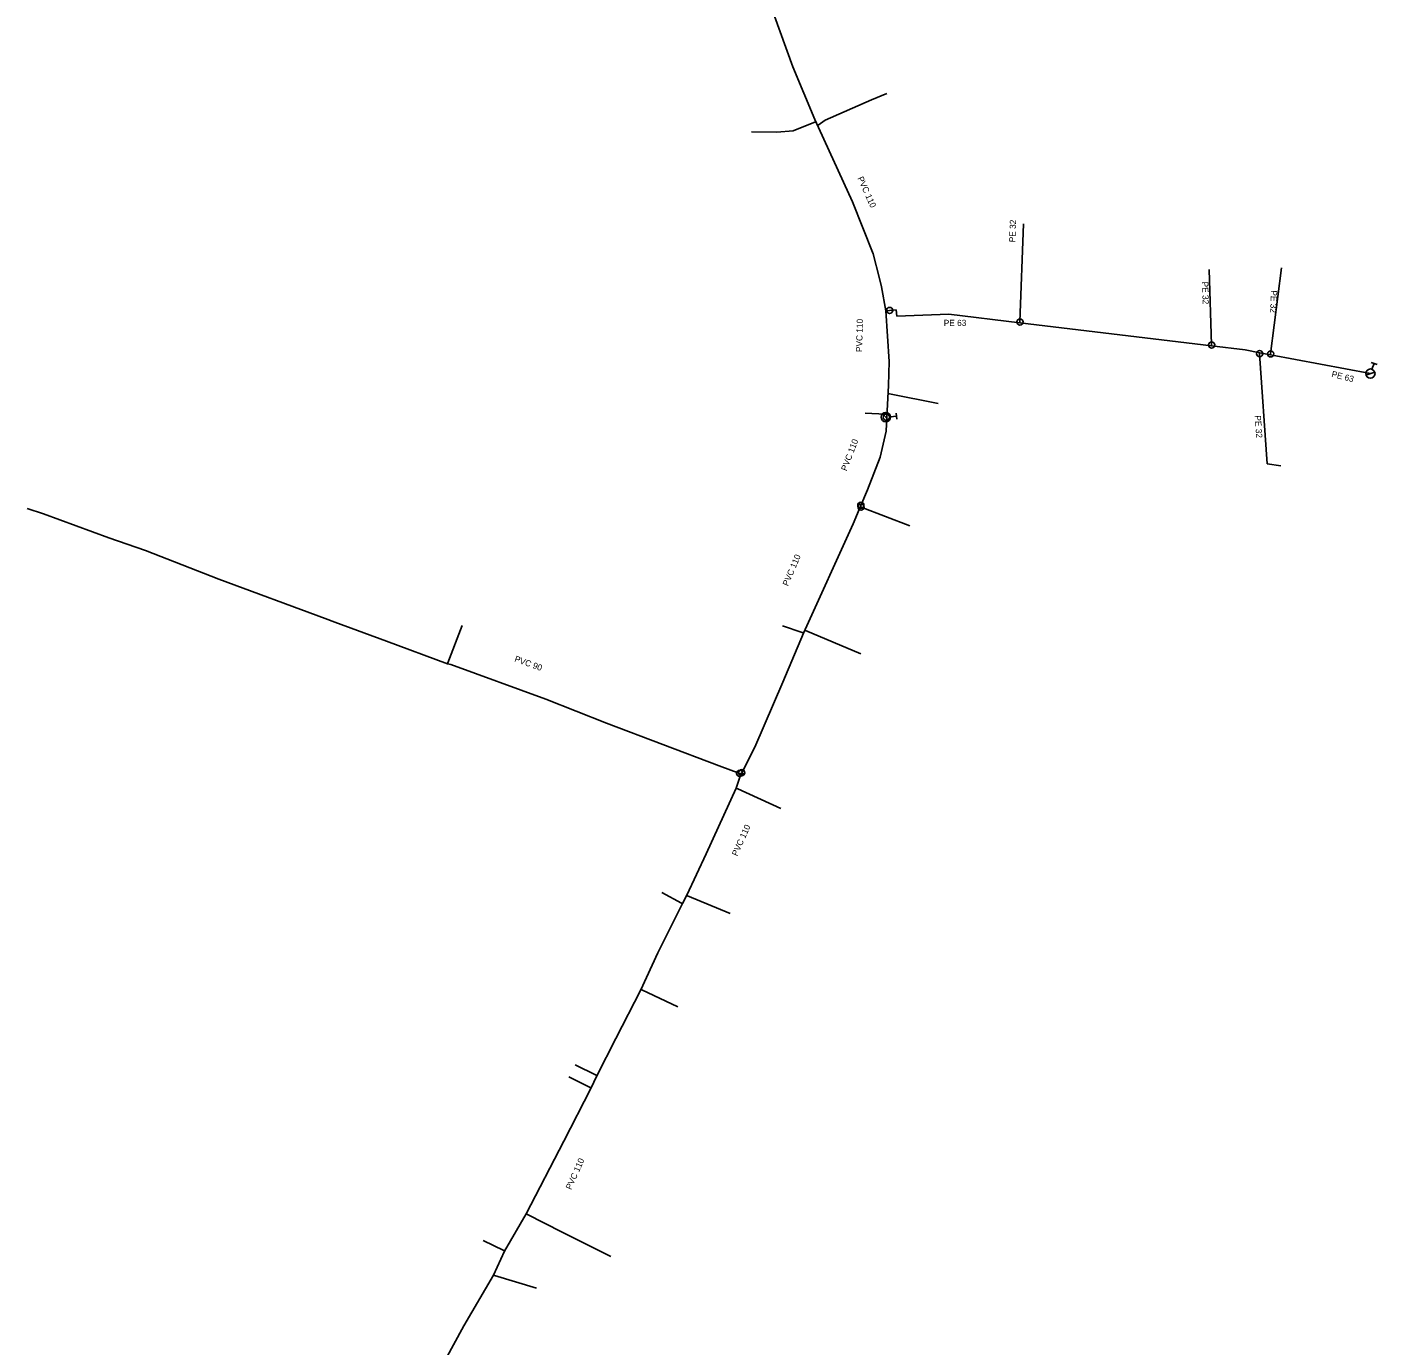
# Model space of a CAD drawing. Extents: x -643485 to -643037, y -1068047 to -1067198.
# Drawn here: x -643415.5 to -643197.8, y -1067622.7 to -1067410.2 of the extents above; entities that cross this region are included whole.
import ezdxf

# ---------------------------------------------------------------- set-up
doc = ezdxf.new("R2010")
doc.units = 0
doc.layers.add('Level 0', color=7, linetype='Continuous')

msp = doc.modelspace()

# ---------------------------------------------------------------- linework, layer by layer
at = {"layer": 'Level 0'}
for p, q in [((-643298.16, -1067399.49), (-643292.02, -1067416.61)), ((-643292.02, -1067416.61), (-643288.44, -1067425.08)), ((-643279.34, -1067421.94), (-643276.87, -1067420.89)), ((-643286.81, -1067425.21), (-643279.34, -1067421.94)), ((-643288.34, -1067425.46), (-643291.96, -1067426.89)), ((-643288.44, -1067425.08), (-643282.4, -1067438.35)), ((-643288.27, -1067425.43), (-643288.34, -1067425.46)), ((-643288, -1067426.05), (-643287.91, -1067426.01)), ((-643287.91, -1067426.01), (-643286.81, -1067425.21)), ((-643294.59, -1067427.13), (-643298.7, -1067427.08)), ((-643291.96, -1067426.89), (-643294.59, -1067427.13)), ((-643282.4, -1067438.35), (-643279.06, -1067446.74)), ((-643255.39, -1067457.73), (-643254.81, -1067441.89)), ((-643279.06, -1067446.74), (-643278.04, -1067450.74)), ((-643224.48, -1067461.45), (-643224.87, -1067449.25)), ((-643214.96, -1067462.88), (-643213.19, -1067448.99)), ((-643278.04, -1067450.74), (-643277.72, -1067452.07)), ((-643277.72, -1067452.07), (-643277, -1067455.94)), ((-643276.41, -1067455.88), (-643277, -1067455.94)), ((-643277, -1067455.94), (-643276.5, -1067464.09)), ((-643275.36, -1067455.76), (-643276.41, -1067455.88)), ((-643275.26, -1067456.82), (-643275.36, -1067455.76)), ((-643266.83, -1067456.5), (-643275.26, -1067456.82)), ((-643255.4, -1067457.88), (-643266.83, -1067456.5)), ((-643255.4, -1067457.88), (-643255.39, -1067457.73)), ((-643224.5, -1067461.6), (-643255.4, -1067457.88)), ((-643224.5, -1067461.6), (-643224.48, -1067461.45)), ((-643219.09, -1067462.25), (-643224.5, -1067461.6)), ((-643216.73, -1067462.7), (-643219.09, -1067462.25)), ((-643216.73, -1067462.7), (-643216.74, -1067462.85)), ((-643216.74, -1067462.85), (-643215.53, -1067480.6)), ((-643215, -1067463.03), (-643216.73, -1067462.7)), ((-643215, -1067463.03), (-643214.96, -1067462.88)), ((-643198.88, -1067466.07), (-643215, -1067463.03)), ((-643276.5, -1067464.09), (-643276.6, -1067467.97)), ((-643198.75, -1067464.25), (-643197.81, -1067464.6)), ((-643198.62, -1067465.37), (-643198.28, -1067464.43)), ((-643199.59, -1067466.3), (-643198.17, -1067465.84)), ((-643276.6, -1067467.97), (-643276.84, -1067473.09)), ((-643276.66, -1067469.27), (-643276.41, -1067469.32)), ((-643276.41, -1067469.32), (-643268.56, -1067470.89)), ((-643277.08, -1067472.6), (-643280.36, -1067472.42)), ((-643277.53, -1067472.53), (-643276.51, -1067473.63)), ((-643276.81, -1067472.62), (-643277.08, -1067472.6)), ((-643276.93, -1067473.09), (-643277.02, -1067473.08)), ((-643276.84, -1067473.09), (-643276.97, -1067475.34)), ((-643276.84, -1067473.09), (-643276.93, -1067473.09)), ((-643276.27, -1067473.01), (-643275.28, -1067472.93)), ((-643275.32, -1067472.43), (-643275.23, -1067473.42)), ((-643276.97, -1067475.34), (-643277.95, -1067479.53)), ((-643277.95, -1067479.53), (-643279.95, -1067484.78)), ((-643215.53, -1067480.6), (-643213.3, -1067480.95)), ((-643279.95, -1067484.78), (-643281.04, -1067487.31)), ((-643412.82, -1067488.7), (-643415.5, -1067487.82)), ((-643402.33, -1067492.53), (-643412.82, -1067488.7)), ((-643281.04, -1067487.31), (-643282.3, -1067490.28)), ((-643281.14, -1067487.54), (-643281, -1067487.59)), ((-643281, -1067487.59), (-643273.15, -1067490.59)), ((-643282.3, -1067490.28), (-643290.28, -1067507.91)), ((-643396.37, -1067494.58), (-643402.33, -1067492.53)), ((-643384.57, -1067499.21), (-643396.37, -1067494.58)), ((-643367.44, -1067505.55), (-643384.57, -1067499.21)), ((-643365.84, -1067506.16), (-643367.44, -1067505.55)), ((-643357.52, -1067509.19), (-643365.84, -1067506.16)), ((-643347.64, -1067512.69), (-643345.35, -1067506.71)), ((-643290.52, -1067507.83), (-643293.65, -1067506.73)), ((-643290.28, -1067507.91), (-643293.63, -1067515.84)), ((-643290.28, -1067507.91), (-643290.52, -1067507.83)), ((-643290.07, -1067507.44), (-643289.96, -1067507.48)), ((-643289.96, -1067507.48), (-643281.07, -1067511.26)), ((-643347.71, -1067512.84), (-643357.52, -1067509.19)), ((-643347.71, -1067512.84), (-643347.64, -1067512.69)), ((-643347.14, -1067512.95), (-643347.71, -1067512.84)), ((-643331.84, -1067518.56), (-643347.14, -1067512.95)), ((-643293.63, -1067515.84), (-643298.13, -1067526.29)), ((-643322.04, -1067522.42), (-643331.84, -1067518.56)), ((-643303.88, -1067529.31), (-643322.04, -1067522.42)), ((-643298.13, -1067526.29), (-643300.25, -1067530.43)), ((-643300.58, -1067530.53), (-643303.88, -1067529.31)), ((-643301.12, -1067532.94), (-643300.4, -1067530.67)), ((-643300.4, -1067530.67), (-643300.58, -1067530.53)), ((-643300.25, -1067530.43), (-643300.4, -1067530.67)), ((-643305.99, -1067543.53), (-643301.12, -1067532.94)), ((-643301.12, -1067532.94), (-643300.89, -1067533.04)), ((-643300.89, -1067533.04), (-643293.94, -1067536.17)), ((-643309.08, -1067550.19), (-643305.99, -1067543.53)), ((-643309.96, -1067551.44), (-643313.13, -1067549.74)), ((-643309.82, -1067551.49), (-643309.08, -1067550.19)), ((-643309.08, -1067550.19), (-643308.97, -1067550.27)), ((-643308.97, -1067550.27), (-643302.11, -1067553.13)), ((-643313.79, -1067559.45), (-643309.82, -1067551.49)), ((-643309.82, -1067551.49), (-643309.96, -1067551.44)), ((-643316.5, -1067565.42), (-643313.79, -1067559.45)), ((-643320.57, -1067573.28), (-643316.5, -1067565.42)), ((-643316.5, -1067565.42), (-643316.36, -1067565.46)), ((-643316.36, -1067565.46), (-643310.56, -1067568.2)), ((-643323.64, -1067579.28), (-643320.57, -1067573.28)), ((-643323.73, -1067579.19), (-643327.1, -1067577.52)), ((-643324.71, -1067581.18), (-643328.11, -1067579.44)), ((-643324.58, -1067581.34), (-643323.64, -1067579.28)), ((-643323.64, -1067579.28), (-643323.73, -1067579.19)), ((-643328.94, -1067589.85), (-643324.58, -1067581.34)), ((-643324.58, -1067581.34), (-643324.71, -1067581.18)), ((-643335.01, -1067601.57), (-643328.94, -1067589.85)), ((-643338.51, -1067607.57), (-643335.01, -1067601.57)), ((-643335.01, -1067601.57), (-643334.88, -1067601.6)), ((-643334.88, -1067601.6), (-643329.19, -1067604.49)), ((-643329.19, -1067604.49), (-643321.35, -1067608.45)), ((-643338.61, -1067607.49), (-643341.92, -1067605.84)), ((-643340.27, -1067611.45), (-643338.51, -1067607.57)), ((-643338.51, -1067607.57), (-643338.61, -1067607.49)), ((-643345.05, -1067619.61), (-643340.27, -1067611.45)), ((-643340.27, -1067611.45), (-643340.12, -1067611.5)), ((-643340.12, -1067611.5), (-643333.33, -1067613.53)), ((-643350, -1067628.62), (-643345.05, -1067619.61))]:
    msp.add_line(p, q, dxfattribs=at)
for centre, radius in [((-643276.41, -1067455.88), 0.5), ((-643255.39, -1067457.73), 0.5), ((-643224.48, -1067461.45), 0.5), ((-643216.74, -1067462.85), 0.5), ((-643214.96, -1067462.88), 0.5), ((-643198.88, -1067466.07), 0.75), ((-643277.02, -1067473.08), 0.75), ((-643276.93, -1067473.09), 0.5), ((-643281.04, -1067487.31), 0.5), ((-643281, -1067487.59), 0.5), ((-643300.58, -1067530.53), 0.5), ((-643300.25, -1067530.43), 0.5)]:
    msp.add_circle(centre, radius, dxfattribs=at)

# ---------------------------------------------------------------- texts
for s, rotation, p in [('PVC 110', 294.149, (-643281.62, -1067434.55)), ('PE 32', 87.903, (-643256.14, -1067444.9)), ('PE 32', 271.831, (-643226.03, -1067451.25)), ('PE 32', 267.52, (-643214.89, -1067452.62)), ('PVC 110', 88.524, (-643280.84, -1067462.6)), ('PE 63', 345.999, (-643205.22, -1067466.58)), ('PE 32', 273.9, (-643217.53, -1067472.84)), ('PVC 110', 69.146, (-643283.34, -1067481.85)), ('PVC 110', 67.099, (-643292.79, -1067500.41)), ('PVC 90', 339.989, (-643336.98, -1067512.46)), ('PVC 110', 65.993, (-643300.98, -1067543.95)), ('PVC 110', 65.993, (-643327.77, -1067597.75))]:
    msp.add_text(s, height=1, rotation=rotation, dxfattribs=at).set_placement(p)
msp.add_text('PE 63', height=1, dxfattribs=at).set_placement((-643267.67, -1067458.39))

doc.saveas('drawing.dxf')
